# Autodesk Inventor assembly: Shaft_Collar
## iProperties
Created: 2008-04
Part Number: Shaft_Collar
Document SubType Name: Assembly
Mass: 0.943808 g
Surface Area: 5.9402 cm^2
Volume: 0.571592 cm^3
Density: 1.65119 g/cm^3
